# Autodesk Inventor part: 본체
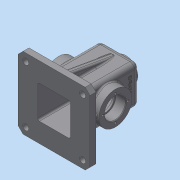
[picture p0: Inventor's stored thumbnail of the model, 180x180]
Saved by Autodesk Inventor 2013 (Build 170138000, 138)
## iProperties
Created: 2018-10
Part Number: 본체
Material: 일반
Document SubType Name: Modeling
Designer: Administrator
Density: 1 g/cm^3
Author: Administrator
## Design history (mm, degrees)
sketch "스케치1"
  geometry: L1 (-32.5, 110)-(32.5, 110); L2 (32.5, 110)-(32.5, 0); L3 (32.5, 0)-(-32.5, 0); L4 (-32.5, 0)-(-32.5, 110); 2 further points
  constraints: 8 end point, 2 parallel, 1 coincident, 1 horizontal, 1 midpoint, 1 perpendicular
  dimensions: "d0" = 65 distance of L1.start L1.end; "d2" = 110 distance of L1.end L2.end
extrude "돌출1" new body sketch "스케치1" stored distance "d3" = 65; taper "d4" = 0 deg
feature "쉘1" dims "d5" = 5
sketch "스케치2"
  geometry: L1 (65, 0)-(65, -65) reference; L2 (-27.5, -92.5)-(92.5, -92.5); L3 (92.5, -92.5)-(92.5, 27.5); L4 (92.5, 27.5)-(-27.5, 27.5); L5 (-27.5, 27.5)-(-27.5, -92.5); L6 (-27.5, -92.5)-(92.5, 27.5); L7 (92.5, -92.5)-(-27.5, 27.5); L8 (5, -60)-(60, -60) reference; L9 (60, -60)-(60, -5) reference; L10 (60, -5)-(5, -5) reference; L11 (5, -5)-(5, -60) reference; L12 (65, -65)-(0, -65) reference; L13 (0, -65)-(0, 0) reference; L14 (0, 0)-(65, 0) reference; L15 (65, 0)-(65, -65) reference; 1 further point
  constraints: 12 end point, 2 midpoint, 2 parallel, 1 horizontal, 1 perpendicular
  dimensions: "d6" = 120 distance of L3.end L4.end; "d8" = 120 distance of L2.end L3.end
extrude "돌출2" join sketch "스케치2" distance "d9" = 10; taper "d10" = 0 deg
chamfer "모따기1" distance "d11" = 8; stored, may be unused: second distance "d12" = 2, angle "d13" = 45 deg
sketch "스케치3"
  geometry: C1 r 5 at (-15, 80); 1 further point
  constraints: 1 centre point
  dimensions: "d16" = 10 diameter of C1; "d18" = 47.5 horizontal distance of point (32.5, 32.5) C1.centre; "d19" = 47.5 horizontal distance of point (32.5, 32.5) C1.centre
extrude "돌출3" cut sketch "스케치3" stored distance "d20" = 10; taper "d21" = 0 deg
fillet "모깎기1" dims "d22" = 8
fillet "모깎기2" dims "d23" = 8
sketch "스케치5"
  geometry: L1 (84.5, -10)-(-35.5, -10) reference; L2 (-35.5, -10)-(-35.5, 0) reference; L3 (-35.5, 0)-(0, 0) reference; L4 (0, 0)-(0, 92) reference; L5 (0, 92)-(49, 92) reference; L6 (49, 92)-(49, 0) reference; L7 (0, 0)-(49, 0) reference; L8 (84.5, 0)-(84.5, -10) reference; L9 (49, 0)-(84.5, 0) reference; L10 (76.5, -10)-(-27.5, -10) reference; L11 (84.5, -10)-(-35.5, -10) reference; L12 (-35.5, -10)-(-35.5, 0) reference; L13 (-35.5, 0)-(0, 0) reference; L14 (0, 0)-(0, 92) reference; L15 (0, 92)-(49, 92) reference; L16 (49, 92)-(49, 0) reference; L17 (0, 0)-(49, 0) reference; L18 (84.5, 0)-(84.5, -10) reference; L19 (49, 0)-(84.5, 0) reference; L20 (84.5, -10)-(-35.5, -10) reference; L21 (-35.5, -10)-(-35.5, 0) reference; L22 (-35.5, 0)-(0, 0) reference; L23 (0, 0)-(0, 92) reference; L24 (0, 92)-(49, 92) reference; L25 (49, 92)-(49, 0) reference; L26 (0, 0)-(49, 0) reference; L27 (84.5, 0)-(84.5, -10) reference; L28 (49, 0)-(84.5, 0) reference; C1 r 27.5 at (24.5, 45); 2 further points
  constraints: 1 centre point, 1 midpoint, 1 vertical alignment
  dimensions: "d37" = 55 diameter of C1; "d39" = 55 distance from line of L1 C1.centre
extrude "돌출5" join sketch "스케치5" distance "d40" = 15; taper "d41" = 0 deg
sketch "스케치6"
  geometry: C1 r 27.5 at (0, 0) reference; C2 r 15 at (0, 0); 1 further point
  constraints: 1 centre point, 1 coincident
  dimensions: "d44" = 30 diameter of C2
extrude "돌출6" cut sketch "스케치6" stored distance "d45" = 15; taper "d46" = 0 deg
sketch "스케치7"
  geometry: C1 r 15 at (0, 0) reference; C2 r 27.5 at (0, 0) reference; C3 r 17.5 at (0, 0); 1 further point
  constraints: 1 centre point, 1 coincident
  dimensions: "d47" = 35 diameter of C3
extrude "돌출7" cut sketch "스케치7" distance "d48" = 17; taper "d49" = 0 deg
chamfer "모따기2" distance "d50" = 1; stored, may be unused: second distance "d51" = 2, angle "d52" = 45 deg
fillet "모깎기14" dims "d89" = 3
sketch "스케치8"
  geometry: C1 r 27.5 at (0, 0) reference; 2 further points
  constraints: 1 vertical alignment
  dimensions: "d53" = 21 distance of C1.centre point (0, 21)
hole "구멍2" sketch "스케치8" at (0, 21) diameter "d54" = 3.459; stored, may be unused: countersink angle "d58" = 90 deg, drill point angle "d60" = 118 deg; dims "d55" = 8, "d56" = 4, "d57" = 2, "d59" = 10
sketch "스케치9"
  geometry: L1 (27.28, 44.953)-(10, 48); L2 (10, 60)-(0, 60) reference; L3 (10, 52)-(10, -52) reference; 1 further point
  constraints: 2 end point, 1 point on line
  dimensions: "d64" = 10 deg angle of L2 L1; "d65" = 12 distance from line of L2 L1.end
feature "리브1" sketch "스케치9" dims "d66" = 1, "d67" = 10, "d68" = 0, "d69" = 0, "d70" = 1, "d71" = 1
fillet "모깎기15" dims "d90" = 3
fillet "모깎기4" dims "d72" = 3
fillet "모깎기5" dims "d73" = 3
fillet "모깎기6" dims "d74" = 3
fillet "모깎기7" dims "d75" = 3
sketch "스케치10"
  geometry: L1 (-42.5, 21.823)-(-42.5, 12.093); L2 (-27.5, 105)-(-27.5, 0) reference; 1 further point
  constraints: 2 end point, 1 vertical
  dimensions: "d76" = 15 distance between parallel lines of L2 L1
feature "리브2" sketch "스케치10" dims "d77" = 1, "d78" = 6, "d79" = 0, "d80" = 0, "d81" = 1, "d82" = 1
fillet "모깎기8" dims "d83" = 3
fillet "모깎기9" dims "d84" = 3
fillet "모깎기10" dims "d85" = 1
fillet "모깎기11" dims "d86" = 0.3
fillet "모깎기12" dims "d87" = 3
fillet "모깎기13" dims "d88" = 3
sketch "스케치11"
  geometry: L1 (5.728, 18)-(43.272, 18) reference; L2 (-8, 0)-(-8, -91) reference; 2 further points
  constraints: 1 other
  dimensions: "d91" = 26 distance from line of point (24.5, -8) L1; "d92" = 32.5 distance from line of point (24.5, -8) L2
feature "엠보싱1" sketch "스케치11" dims "d6" = 120, "d8" = 120, "d93" = 0.5, "d94" = 0
fillet "모깎기16" dims "d95" = 3
fillet "모깎기17" dims "d96" = 3
node "작업 평면1"
sketch "스케치12"
  geometry: C1 r 20 at (24.5, 24.5); 1 further point
  constraints: 1 centre point, 1 coincident
  dimensions: "d98" = 40 diameter of C1
extrude "돌출8" join sketch "스케치12" stored distance "d99" = 17; taper "d100" = 7 deg
hole "구멍3" diameter "d103" = 22.835; stored, may be unused: countersink angle "d107" = 90 deg, drill point angle "d109" = 0 deg; dims "d101" = 10, "d102" = 10, "d104" = 25, "d105" = 4, "d106" = 2, "d108" = 30
fillet "모깎기18" dims "d110" = 3
chamfer "모따기3" distance "d111" = 1; stored, may be unused: second distance "d112" = 2, angle "d113" = 45 deg
node "솔리드1"
mirror "대칭1"
mirror "대칭2"
pattern_circular "원형 패턴1" dims angle "d62" = 360 deg
mirror "대칭3"
mirror "대칭4"
mirror "대칭5"
node "절단 모서리 투영1"
node "절단 모서리 투영2"
node "절단 모서리 투영3"
node "절단 모서리 투영4"
